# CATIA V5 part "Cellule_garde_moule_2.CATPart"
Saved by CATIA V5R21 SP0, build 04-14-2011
Part number: Moule_cellule_garde
Bounding box of the stored display mesh (mm): x -18 to 18, y -72 to 72, z -11 to 0
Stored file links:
  C:\Users\zerma\Pictures\Stage Stomate\Moule\Cellule_garde_moule_2.CATPart
  Product1.CATProduct
  C:\Users\zerma\Pictures\Moule\Moule_v1.CATPart
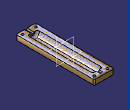
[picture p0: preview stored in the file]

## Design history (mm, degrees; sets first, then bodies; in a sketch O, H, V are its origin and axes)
Body1 (main body)
  Sketch1 on yz-plane, origin (0, 0, 0), H (0, 1, 0), V (0, 0, 1)
    line L1 (-95, -12.5) -> (95, -12.5)
    point P1 (-95, -12.5)
    line L2 (-100, -15) -> (100, -15)
    point P3 (-100, -15)
    line L3 (-95, -12.5) -> (-95, 0)
    point P5 (-95, 0)
    line L4 (-100, -15) -> (-100, 0)
    point P6 (-100, 0)
    line L5 (-95, 0) -> (-100, 0)
    point P7 (100, 0)
    point P8 (100, -15)
    line L6 (100, -15) -> (100, 0)
    point P9 (95, 0)
    line L7 (95, 0) -> (100, 0)
    point P10 (95, -12.5)
    line L8 (95, -12.5) -> (95, 0)
    distance L1 H = 12.5
    distance L1 L2 = 2.5
    length L4 = 15
    distance L4 L3 = 5
    length L1 = 190
    length L2 = 200
    distance V L3 = 95
    horizontal: L1 H, L2 H, L5 H
    vertical: L3 V, L4 V
    symmetry: P6 P7 V, P3 P8 V, L4 L6 V, P5 P9 V, L5 L7 V, P1 P10 V, L3 L8 V
  Shaft1: profile Sketch1, axis Sketch1.H, angle 360
  Sketch2 on face of Shaft1 from Sketch1.L4, origin (0, -100, 0), H (1, 0, 0), V (0, 0, 1)
    line L1 (-10, 2.5) -> (10, 2.5)
    line L2 (10, 2.5) -> (10, -2.5)
    line L3 (10, -2.5) -> (-10, -2.5)
    line L4 (-10, -2.5) -> (-10, 2.5)
    length L2 = 5
    length L1 = 20
    horizontal: L1 H, L3 H
    vertical: L2 V, L4 V
    symmetry: L3 L1 H, L4 L2 V
  Pad1: profile Sketch2, direction (0, -1, 0), length 15
  Sketch3 on face of Pad1 from Sketch2.L1, origin (0, 0, 2.5), H (1, 0, 0), V (0, 1, 0)
    circle A1 centre (0, -107.5) radius 2.5
    point P1 (0, -107.5)
    reference intersected line E1 (14.7902, -100) -> (-14.7902, -100) from face of Shaft1 from Sketch1.L4
    radius A1 = 2.5
    distance P1 E1 = 7.5
    coincidence: P1 V
  Pocket1: profile Sketch3, direction (0, 0, -1), length 5, mirrored extent
  Fillet1: radius 2, on edge [face of Pad1 from Sketch2.L4 | end face of Pad1]; edge [face of Pad1 from Sketch2.L1 | end face of Pad1]; edge [face of Pad1 from Sketch2.L3 | end face of Pad1]; edge [face of Pad1 from Sketch2.L2 | end face of Pad1]; edge [face of Pad1 from Sketch2.L2 | face of Pad1 from Sketch2.L3]; edge [face of Shaft1 from Sketch1.L4 | face of Pad1 from Sketch2.L3]; edge [face of Pad1 from Sketch2.L3 | face of Pad1 from Sketch2.L4]; edge [face of Pocket1 from Sketch3.A1 | face of Pad1 from Sketch2.L3]; edge [face of Pad1 from Sketch2.L4 | face of Pad1 from Sketch2.L1]; edge [face of Pad1 from Sketch2.L1 | face of Pad1 from Sketch2.L2]; edge [face of Shaft1 from Sketch1.L4 | face of Pad1 from Sketch2.L1]; edge [face of Shaft1 from Sketch1.L4 | face of Pad1 from Sketch2.L4]; edge [face of Shaft1 from Sketch1.L4 | face of Pad1 from Sketch2.L2]; face of Pad1 from Sketch2.L1
  Mirror1: of Pad1, Pocket1, Fillet1, about zx-plane
  Fillet2: radius 4, on edge [face of Shaft1 from Sketch1.L2 | face of Shaft1 from Sketch1.L6]; edge [face of Shaft1 from Sketch1.L4 | face of Shaft1 from Sketch1.L2]
Body2
  Sketch4 on xy-plane, origin (0, 0, 0), H (1, 0, 0), V (0, 1, 0)
    line L1 (18, 72) -> (18, -72)
    line L2 (18, -72) -> (-18, -72)
    line L3 (-18, -72) -> (-18, 72)
    line L4 (-18, 72) -> (18, 72)
    length L3 = 144
    length L4 = 36
    vertical: L1 V, L3 V
    horizontal: L2 H, L4 H
    equidistance: L1 L3 O, L2 L4 O
  Pad2: profile Sketch4, direction (0, 0, -1), length 11
  Body3
    Sketch5 on yz-plane, origin (0, 0, 0), H (0, 1, 0), V (0, 0, 1)
      line L1 (-55, -4.5) -> (55, -4.5)
      point P1 (-55, -4.5)
      point P2 (55, -4.5)
      line L2 (-60, -9) -> (60, -9)
      point P3 (-60, -9)
      point P4 (60, -9)
      line L3 (-55, -4.5) -> (-55, 0)
      point P5 (-55, 0)
      line L4 (-60, -9) -> (-60, -2.5)
      point P6 (-60, -2.5)
      point P7 (60, -2.5)
      point P8 (60, -9)
      line L5 (60, -9) -> (60, -2.5)
      point P9 (55, 0)
      point P10 (55, -4.5)
      line L6 (55, -4.5) -> (55, 0)
      line L7 (-60, -2.5) -> (-72, -2.5)
      line L8 (-72, -2.5) -> (-72, 0)
      line L9 (-72, 0) -> (-55, 0)
      point P13 (-55, 0)
      line L10 (60, -2.5) -> (67, -2.5)
      line L11 (67, -2.5) -> (67, 0)
      line L12 (67, 0) -> (55, 0)
      distance L1 H = 4.5
      distance L1 L2 = 4.5
      length L4 = 6.5
      distance L4 L3 = 5
      distance V L3 = 55
      length L9 = 17
      length L12 = 12
      length L11 = 2.5
      horizontal: L1 H, L2 H, L7 H, L9 H, L10 H, L12 H
      vertical: L3 V, L4 V, L8 V, L11 V
      symmetry: P6 P7 V, P3 P8 V, L4 L5 V, P5 P9 V, P1 P10 V, L3 L6 V
      coincidence: P13 P5, P2 P10, P4 P8
    Shaft2: profile Sketch5, axis Sketch5.H, angle 360
  Remove1: tool Body3
  Sketch6 on face of Shaft2 from Sketch5.L6, origin (0, 55, 0), H (-1, 0, 0), V (0, 0, 1)
    circle A1 centre (0, 0) radius 4.5
    reference projected circle E1 centre (0, 0) radius 4.5 from edge [face of Shaft2 from Sketch5.L1 | face of Shaft2 from Sketch5.L6]
    reference projected circle E2 centre (0, 0) radius 4.5 from edge [face of Shaft2 from Sketch5.L1 | face of Shaft2 from Sketch5.L6]
    coincidence: A1 E1
    concentricity: A1 E2
  Pocket2: profile Sketch6, direction (0, -1, 0), up to face of Shaft2 from Sketch5.L3
  Sketch7 on end face of Pad2, origin (0, 0, -11), H (1, 0, 0), V (0, -1, 0)
    circle A1 centre (12, 66) radius 2.25
    point P1 (12, 66)
    circle A2 centre (12, -66) radius 2.25
    circle A3 centre (-12, 66) radius 2.25
    circle A4 centre (-12, -66) radius 2.25
    reference projected line E1 (18, 72) -> (18, -72) from edge [end face of Pad2 | face of Pad2 from Sketch4.L1]
    reference projected line E2 (-18, 72) -> (18, 72) from edge [end face of Pad2 | face of Pad2 from Sketch4.L2]
    radius A1 = 2.25
    distance P1 E1 = 6
    distance P1 E2 = 6
    symmetry: A1 A2 H, A1 A3 V, A3 A4 H
  Pocket3: profile Sketch7, direction (0, 0, 1), length 50, mirrored extent
  Fillet3: radius 4, on edge [face of Shaft2 from Sketch5.L5 | face of Shaft2 from Sketch5.L2]
  Fillet4: radius 4, on edge [face of Shaft2 from Sketch5.L2 | face of Shaft2 from Sketch5.L4]
  Chamfer1: length 2, angle 45, on edge [face of Pad2 from Sketch4.L3 | face of Pad2 from Sketch4.L2]; edge [end face of Pad2 | face of Pad2 from Sketch4.L2]; edge [face of Pad2 from Sketch4.L2 | face of Pad2 from Sketch4.L1]; edge [end face of Pad2 | face of Pad2 from Sketch4.L1]; edge [end face of Pad2 | face of Pad2 from Sketch4.L3]; edge [end face of Pad2 | face of Pad2 from Sketch4.L4]; edge [face of Pad2 from Sketch4.L4 | face of Pad2 from Sketch4.L3]; edge [face of Pad2 from Sketch4.L1 | face of Pad2 from Sketch4.L4]
  CLDGeom1 "Maillage.1"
